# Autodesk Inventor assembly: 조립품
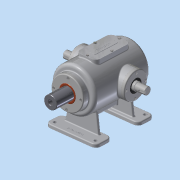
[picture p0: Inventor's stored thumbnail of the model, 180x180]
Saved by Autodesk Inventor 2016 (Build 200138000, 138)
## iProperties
Created: 2018-11
Part Number: 조립품
Material: 일반
Document SubType Name: Assembly
Designer: user
Mass: 8191.29 g
Surface Area: 4241.81 cm^2
Volume: 1855.49 cm^3
Density: 4.41462 g/cm^3
Author: user
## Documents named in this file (15)
- C:\Users\user\Desktop\381121V1008\381121V1008\조립품.iam
- C:\Users\user\Desktop\381121V1008\381121V1008\가변스프링.ipt
- C:\Users\user\Desktop\381121V1008\381121V1008\베어링 6205.ipt
- 베어링 6205.ipt
- C:\Users\user\Desktop\381121V1008\381121V1008\본체.ipt
- C:\Users\user\Desktop\381121V1008\381121V1008\볼트 M4x0.7.ipt
- C:\Users\user\Desktop\381121V1008\381121V1008\부시.ipt
- C:\Users\user\Desktop\381121V1008\381121V1008\상부커버.ipt
- C:\Users\user\Desktop\381121V1008\381121V1008\슬라이드 커버.ipt
- C:\Users\user\Desktop\381121V1008\381121V1008\슬라이드.ipt
- C:\Users\user\Desktop\381121V1008\381121V1008\오일실.ipt
- 오일실.ipt
- C:\Users\user\Desktop\381121V1008\381121V1008\육각머리볼트 M4.ipt
- C:\Users\user\Desktop\381121V1008\381121V1008\축 커버.ipt
- C:\Users\user\Desktop\381121V1008\381121V1008\편심축.ipt
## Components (13 placed, 2 different names)
1. 가변스프링:1
2. M4x0.7:2
3. M4x0.7:4
4. M4x0.7:5
5. M4x0.7:6
6. M4x0.7:1
7. M4x0.7:7
8. M4x0.7:8
9. M4x0.7:9
10. M4x0.7:3
11. M4x0.7:10
12. M4x0.7:11
13. M4x0.7:12
